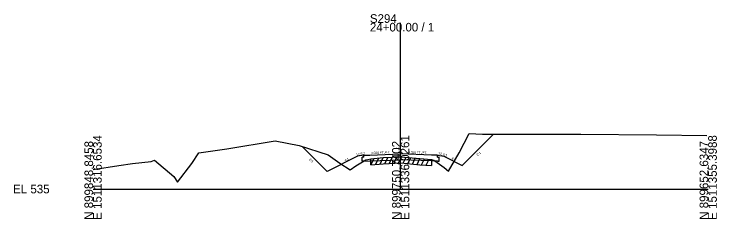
# Model space of a CAD drawing. Extents: x 974 to 2203, y -10 to 19041.
# Drawn here: x 1974.3 to 2202.8, y 7990.3 to 8056.8 of the extents above; entities that cross this region are included whole.
import ezdxf

# ---------------------------------------------------------------- set-up
doc = ezdxf.new("R2010")
doc.units = 0
for name, color, linetype in [('RD_GPK_XS_Cell', 7, 'Continuous'), ('RD_XS_Base', 7, 'Continuous'), ('RD_XS_EarthShd', 7, 'Continuous'), ('RD_XS_ExGround', 7, 'Continuous'), ('RD_XS_ExPaveRet', 7, 'Continuous'), ('RD_XS_Pave', 7, 'Continuous'), ('RD_XS_TX_Elev_EX', 7, 'Continuous'), ('RD_XS_TX_Slope', 7, 'Continuous')]:
    doc.layers.add(name, color=color, linetype=linetype)

msp = doc.modelspace()

# ---------------------------------------------------------------- linework, layer by layer
at = {"layer": 'RD_GPK_XS_Cell'}
for p, q in [((2100, 8000), (2100, 8053.93)), ((2000, 8000), (2100, 8000)), ((2100, 8000), (2200, 8000))]:
    msp.add_line(p, q, dxfattribs=at)
at = {"layer": 'RD_XS_Base'}
for p, q in [((2088, 8010.32), (2087.48, 8010.3)), ((2087.48, 8009.03), (2087.48, 8010.3)), ((2088, 8010.32), (2088, 8010.96)), ((2112, 8010.32), (2112, 8010.96)), ((2112, 8010.32), (2112.52, 8010.3)), ((2112.52, 8009.03), (2112.52, 8010.3)), ((2087.98, 8009.05), (2087.48, 8009.03)), ((2087.98, 8009.05), (2090, 8009.13)), ((2090, 8009.13), (2100, 8009.53)), ((2110, 8009.13), (2100, 8009.53)), ((2112.02, 8009.05), (2110, 8009.13)), ((2112.02, 8009.05), (2112.52, 8009.03))]:
    msp.add_line(p, q, dxfattribs=at)
at = {"layer": 'RD_XS_EarthShd'}
for p, q in [((2120, 8007.63), (2130.19, 8017.82)), ((2076.1, 8005.68), (2067.96, 8013.83)), ((2086, 8010.63), (2076.1, 8005.68)), ((2088, 8010.96), (2086, 8010.63)), ((2112, 8010.96), (2114, 8010.63)), ((2114, 8010.63), (2120, 8007.63))]:
    msp.add_line(p, q, dxfattribs=at)
at = {"layer": 'RD_XS_ExGround'}
msp.add_lwpolyline([(2000, 8006.34), (2008.34, 8007.65), (2012.81, 8008.31), (2018.89, 8008.97), (2019.95, 8009.36), (2026.3, 8004.1), (2027.46, 8002.28), (2032.12, 8008.31), (2034.38, 8011.74), (2043.53, 8013.06), (2059.23, 8015.66), (2067.01, 8014.13), (2076.39, 8011.08), (2080.23, 8008.43), (2083.63, 8006.2), (2085.38, 8007.57), (2088.72, 8009.47), (2089.3, 8009.62), (2090.32, 8009.85), (2094.31, 8010.2), (2100.03, 8010.5), (2106.19, 8009.88), (2109.99, 8009.64), (2110.74, 8009.39), (2111.16, 8009.2), (2114.1, 8007.04), (2115.54, 8005.78), (2119.07, 8011.78), (2122.24, 8017.98), (2126.6, 8017.84), (2138.66, 8017.78), (2158.55, 8017.78), (2183.18, 8017.56), (2199.5, 8017.33)], dxfattribs=at)
at = {"layer": 'RD_XS_ExPaveRet'}
for p, q in [((2091.82, 8007.98), (2092.87, 8010.07)), ((2093.32, 8008.11), (2094.37, 8010.21)), ((2094.82, 8008.23), (2095.85, 8010.28)), ((2096.32, 8008.31), (2097.35, 8010.36)), ((2097.82, 8008.39), (2098.85, 8010.44)), ((2099.32, 8008.46), (2100.33, 8010.47)), ((2100.82, 8008.42), (2101.77, 8010.33)), ((2102.32, 8008.27), (2103.27, 8010.18)), ((2090.32, 8007.85), (2091.37, 8009.94)), ((2090.32, 8007.85), (2090.32, 8009.85)), ((2090.32, 8007.85), (2094.31, 8008.2)), ((2094.31, 8008.2), (2100.03, 8008.5)), ((2100.03, 8008.5), (2106.19, 8007.88)), ((2103.82, 8008.12), (2104.77, 8010.03)), ((2105.32, 8007.97), (2106.28, 8009.88)), ((2106.19, 8007.88), (2109.99, 8007.64)), ((2106.82, 8007.84), (2107.79, 8009.78)), ((2108.32, 8007.74), (2109.29, 8009.68)), ((2109.99, 8009.64), (2109.99, 8007.64))]:
    msp.add_line(p, q, dxfattribs=at)
at = {"layer": 'RD_XS_Pave'}
for p, q in [((2088, 8010.96), (2090, 8011.04)), ((2090, 8011.04), (2100, 8011.44)), ((2110, 8011.04), (2100, 8011.44)), ((2112, 8010.96), (2110, 8011.04))]:
    msp.add_line(p, q, dxfattribs=at)

# ---------------------------------------------------------------- texts
at = {"layer": 'RD_GPK_XS_Cell'}
for s, p in [('S294', (2090, 8053.93)), ('24+00.00 / 1', (2090, 8051.13)), ('EL 535', (1974, 7998.6))]:
    msp.add_text(s, height=2.8, dxfattribs=at).set_placement(p)
for s, p in [('E 1511316.6534', (2002.8, 7990)), ('E 1511336.0261', (2102.8, 7990)), ('E 1511355.3988', (2202.8, 7990)), ('N 899848.8458', (2000, 7990)), ('N 899750.7402', (2100, 7990)), ('N 899652.6347', (2200, 7990))]:
    msp.add_text(s, height=2.8, rotation=90, dxfattribs=at).set_placement(p)
at = {"layer": 'RD_XS_TX_Elev_EX'}
msp.add_text('540.25', height=0.75, rotation=90, dxfattribs=at).set_placement((2100, 8010.5))
at = {"layer": 'RD_XS_TX_Slope'}
for s, height, rotation, p in [('0.020 FT./FT.', 0.7518, 357.604, (2102.4, 8011.6)), ('4:1', 0.778, 26.3688, (2081.93, 8008.88)), ('12.5:1', 0.778, 12.7511, (2085.61, 8010.71)), ('0.020 FT./FT.', 0.7518, 2.396, (2090.38, 8011.3)), ('12.5:1', 0.778, 347.2489, (2112.17, 8011.21)), ('4:1', 0.778, 333.6312, (2116.43, 8009.74)), ('2:1', 0.778, 40.6589, (2125.1, 8010.68)), ('2:1', 0.778, 319.3411, (2070.15, 8009.46))]:
    msp.add_text(s, height=height, rotation=rotation, dxfattribs=at).set_placement(p)

doc.saveas('drawing.dxf')
